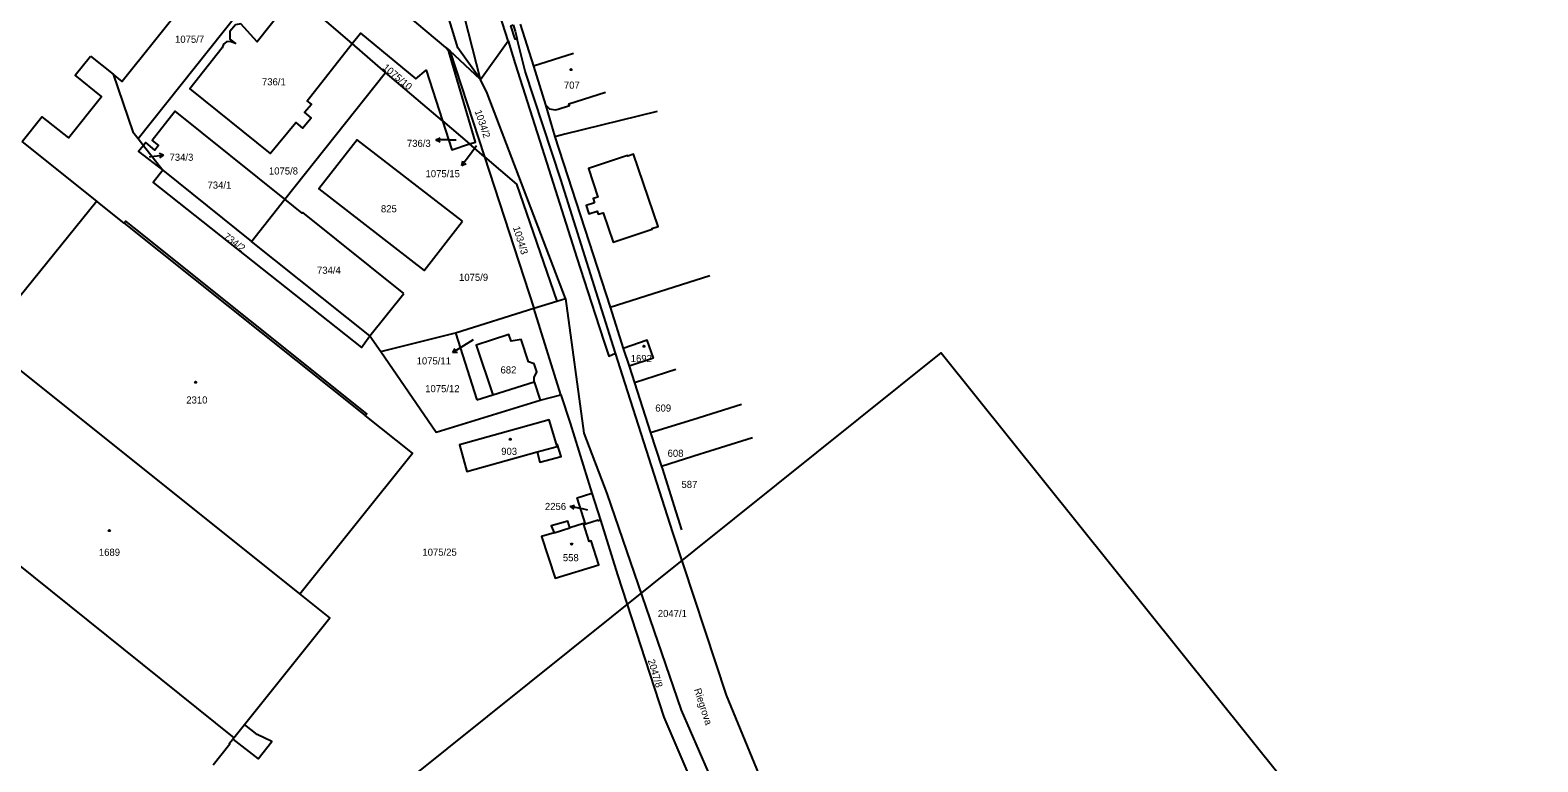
# Model space of a CAD drawing. Extents: x -793666 to -785424, y -1118958 to -1108761.
# Drawn here: x -792344.1 to -791983.5, y -1109605.6 to -1109430.6 of the extents above; entities that cross this region are included whole.
import ezdxf

# ---------------------------------------------------------------- set-up
doc = ezdxf.new("R2010")
doc.units = 0
for name, color, linetype in [('1_2000 - úřady', 7, 'Continuous'), ('Hranice parcel', 7, 'Continuous'), ('Parcelní čísla', 7, 'Continuous'), ('Pop  PČ popisy', 7, 'Continuous'), ('Vnitřní kresba', 7, 'Continuous'), ('Značky budov', 7, 'Continuous')]:
    doc.layers.add(name, color=color, linetype=linetype)

msp = doc.modelspace()

# ---------------------------------------------------------------- linework, layer by layer
at = {"layer": '1_2000 - úřady'}
msp.add_lwpolyline([(-791938.08, -1109742.36), (-792598.01, -1110271.46), (-792786.15, -1110036.8), (-792126.22, -1109507.7)], close=True, dxfattribs=at)
at = {"layer": 'Hranice parcel'}
for p, q in [((-792229.77, -1109433.14), (-792236.48, -1109411.88)), ((-792318.27, -1109456.46), (-792286.75, -1109416.81)), ((-792267.06, -1109433.78), (-792280.76, -1109421.97)), ((-792259.07, -1109440.66), (-792267.06, -1109433.78)), ((-792244.63, -1109434.67), (-792243.68, -1109435.47)), ((-792236.38, -1109442.35), (-792229.77, -1109433.14)), ((-792229.77, -1109433.14), (-792228.05, -1109438.6)), ((-792329.67, -1109436.74), (-792324.22, -1109441.09)), ((-792236.38, -1109442.35), (-792243.68, -1109435.47)), ((-792243.68, -1109435.47), (-792235.42, -1109460.82)), ((-792283.18, -1109471), (-792259.07, -1109440.66)), ((-792245.44, -1109452.28), (-792259.07, -1109440.66)), ((-792220.81, -1109448.38), (-792218.56, -1109456.03)), ((-792245.44, -1109452.28), (-792238.98, -1109457.78)), ((-792194.09, -1109449.98), (-792216.18, -1109455.44)), ((-792318.27, -1109456.46), (-792316.97, -1109458.11)), ((-792216.18, -1109455.44), (-792218.56, -1109456.03)), ((-792218.56, -1109456.03), (-792205.34, -1109496.82)), ((-792328.15, -1109471.45), (-792346.01, -1109457.18)), ((-792316.97, -1109458.11), (-792312.32, -1109464.02)), ((-792235.42, -1109460.82), (-792238.98, -1109457.78)), ((-792235.42, -1109460.82), (-792223.61, -1109497.07)), ((-792312.32, -1109464.02), (-792291.18, -1109481.07)), ((-792291.18, -1109481.07), (-792283.18, -1109471)), ((-792328.15, -1109471.45), (-792350.22, -1109498.79)), ((-792262.87, -1109503.68), (-792291.18, -1109481.07)), ((-792205.34, -1109496.82), (-792181.48, -1109489.21)), ((-792262.87, -1109503.68), (-792254.68, -1109493.51)), ((-792223.61, -1109497.07), (-792218.11, -1109495.38)), ((-792218.11, -1109495.38), (-792216.04, -1109494.77)), ((-792242.33, -1109502.95), (-792223.61, -1109497.07)), ((-792217.14, -1109517.79), (-792223.61, -1109497.07)), ((-792205.34, -1109496.82), (-792202.22, -1109506.7)), ((-792260.21, -1109507.41), (-792242.33, -1109502.95)), ((-792242.33, -1109502.95), (-792237.24, -1109519)), ((-792279.6, -1109565.4), (-792355.19, -1109504.95)), ((-792262.87, -1109503.68), (-792260.21, -1109507.41)), ((-792202.22, -1109506.7), (-792200.82, -1109510.9)), ((-792195, -1109509.05), (-792200.82, -1109510.9)), ((-792237.24, -1109519), (-792233.43, -1109517.79)), ((-792233.43, -1109517.79), (-792223.5, -1109514.64)), ((-792223.5, -1109514.64), (-792222.14, -1109519.07)), ((-792222.14, -1109519.07), (-792217.14, -1109517.79)), ((-792195.72, -1109526.9), (-792193.09, -1109534.9)), ((-792378.05, -1109533.41), (-792295.37, -1109599.83)), ((-792209.71, -1109541.3), (-792207.68, -1109547.79)), ((-792190.54, -1109542.98), (-792188.3, -1109550.06)), ((-792295.37, -1109599.83), (-792295.65, -1109600.16))]:
    msp.add_line(p, q, dxfattribs=at)
for points in [[(-792236.38, -1109442.35), (-792241.83, -1109434.76), (-792242.07, -1109433.96), (-792248.3, -1109413.31), (-792257.02, -1109387.35), (-792267.42, -1109371.57), (-792268.26, -1109370.15)], [(-792244.63, -1109434.67), (-792258.54, -1109423), (-792272.12, -1109411.1)], [(-792299.18, -1109414.18), (-792322.06, -1109442.82), (-792324.22, -1109441.09)], [(-792280.76, -1109421.97), (-792289.81, -1109433.34), (-792293.7, -1109429.04), (-792295.01, -1109429.27), (-792296.35, -1109430.89), (-792296.29, -1109432.67), (-792294.98, -1109433.75), (-792296.26, -1109433.28), (-792297.14, -1109433.34), (-792297.85, -1109433.91), (-792298.14, -1109434.81), (-792305.89, -1109444.59), (-792286.66, -1109460.05), (-792280.52, -1109452.67), (-792278.92, -1109454), (-792276.86, -1109451.51), (-792278.46, -1109450.19), (-792276.83, -1109448.23), (-792277.84, -1109447.42), (-792267.06, -1109433.78)], [(-792267.06, -1109433.78), (-792265.08, -1109431.27), (-792251.85, -1109442.17), (-792249.33, -1109440.1), (-792245.44, -1109452.28)], [(-792227.59, -1109432.68), (-792228.11, -1109432.7), (-792229.13, -1109429.49), (-792228.52, -1109429.29)], [(-792228.52, -1109429.29), (-792228.07, -1109430.77), (-792227.59, -1109432.68)], [(-792226.9, -1109429.15), (-792223.72, -1109439.13), (-792220.81, -1109448.38)], [(-792238.98, -1109457.78), (-792237.53, -1109457.31), (-792243.95, -1109435.69), (-792244.63, -1109434.67)], [(-792204.07, -1109507.78), (-792207.35, -1109497.45), (-792217.13, -1109466.3), (-792225.67, -1109440.37), (-792225.83, -1109439.74), (-792227.59, -1109432.68)], [(-792346.01, -1109457.18), (-792341.33, -1109451.32), (-792334.95, -1109456.33), (-792327.06, -1109446.44), (-792333.34, -1109441.33), (-792329.67, -1109436.74)], [(-792228.05, -1109438.6), (-792221.1, -1109460.59), (-792213.33, -1109485.05), (-792208.98, -1109498.53), (-792206.82, -1109505.15), (-792205.71, -1109508.55), (-792204.07, -1109507.78)], [(-792324.22, -1109441.09), (-792319.52, -1109454.87), (-792318.27, -1109456.46)], [(-792216.04, -1109494.77), (-792234.81, -1109445.64), (-792236.38, -1109442.35)], [(-792220.81, -1109448.38), (-792219.9, -1109449.36), (-792218.42, -1109449.63), (-792217.76, -1109449.42), (-792215.11, -1109448.58), (-792215.24, -1109448.15), (-792206.5, -1109445.38)], [(-792283.18, -1109471), (-792309.4, -1109449.94), (-792314.92, -1109456.94), (-792313.38, -1109458.14), (-792314.26, -1109459.26), (-792316.4, -1109457.43), (-792316.97, -1109458.11)], [(-792245.44, -1109452.28), (-792243.24, -1109459.17), (-792238.98, -1109457.78)], [(-792316.97, -1109458.11), (-792318.18, -1109459.57), (-792312.32, -1109464.02)], [(-792240.71, -1109476.24), (-792265.9, -1109456.76), (-792275.02, -1109468.52), (-792249.86, -1109488.05), (-792240.71, -1109476.24)], [(-792209.1, -1109471.85), (-792211.1, -1109472.52), (-792210.43, -1109474.51), (-792208.44, -1109473.84), (-792208.19, -1109474.6), (-792207.03, -1109474.22), (-792204.68, -1109481.25), (-792195.32, -1109478.16), (-792195.37, -1109478.02), (-792193.91, -1109477.54), (-792199.75, -1109460.2), (-792201.16, -1109460.67), (-792201.21, -1109460.53), (-792210.55, -1109463.67), (-792208.28, -1109470.47), (-792209.44, -1109470.85), (-792209.1, -1109471.85)], [(-792235.42, -1109460.82), (-792227.73, -1109467.37), (-792218.11, -1109495.38)], [(-792312.32, -1109464.02), (-792314.7, -1109467), (-792264.82, -1109506.43), (-792262.87, -1109503.68)], [(-792254.68, -1109493.51), (-792278.86, -1109474.2), (-792278.99, -1109474.36), (-792283.18, -1109471)], [(-792279.6, -1109565.4), (-792252.67, -1109531.71), (-792263.92, -1109522.73), (-792263.58, -1109522.3), (-792319.23, -1109477.86), (-792321.23, -1109476.26), (-792321.58, -1109476.7), (-792327.49, -1109471.98), (-792328.15, -1109471.45)], [(-792216.04, -1109494.77), (-792211.63, -1109526.92), (-792206.15, -1109541.38), (-792188.4, -1109593.25), (-792177.58, -1109617.9), (-792162.42, -1109637.81), (-792158.94, -1109642.01), (-792160.24, -1109643.3), (-792162, -1109644.38)], [(-792223.5, -1109514.64), (-792223.53, -1109513.66), (-792222.86, -1109512.32), (-792223.5, -1109510.33), (-792224.86, -1109509.85), (-792226.61, -1109504.52), (-792229.04, -1109504.98), (-792229.56, -1109503.37), (-792237.41, -1109505.9), (-792233.43, -1109517.79)], [(-792195, -1109509.05), (-792196.47, -1109504.73), (-792202.22, -1109506.7)], [(-792260.21, -1109507.41), (-792246.98, -1109526.69), (-792222.14, -1109519.07)], [(-792153.37, -1109630.69), (-792168.6, -1109611.32), (-792177.54, -1109589.6), (-792190.39, -1109550.74), (-792201.74, -1109515.1), (-792204.07, -1109507.78)], [(-792200.82, -1109510.9), (-792199.56, -1109514.95), (-792195.72, -1109526.9)], [(-792217.14, -1109517.79), (-792214.92, -1109524.55), (-792209.71, -1109541.3)], [(-792173.97, -1109520.08), (-792185.62, -1109523.73), (-792195.72, -1109526.9)], [(-792218.05, -1109529.51), (-792218.22, -1109529.57), (-792219.94, -1109523.79), (-792241.42, -1109529.73), (-792239.61, -1109536.1), (-792222.84, -1109531.45), (-792222.17, -1109533.89), (-792217.04, -1109532.53), (-792218.05, -1109529.51)], [(-792171.33, -1109528.08), (-792182.81, -1109531.68), (-792183.84, -1109532), (-792193.09, -1109534.9)], [(-792193.09, -1109534.9), (-792192.87, -1109535.59), (-792190.54, -1109542.98)], [(-792207.68, -1109547.79), (-792208.17, -1109547.94), (-792208.22, -1109547.8), (-792211.26, -1109548.75), (-792213.24, -1109542.41), (-792209.71, -1109541.3)], [(-792214.99, -1109549.58), (-792215.48, -1109548.01), (-792219.45, -1109549.11), (-792218.77, -1109550.78), (-792221.75, -1109551.71), (-792218.55, -1109561.63), (-792208.1, -1109558.47), (-792209.93, -1109552.72), (-792210.36, -1109552.86), (-792211.71, -1109548.55), (-792214.99, -1109549.58)], [(-792207.68, -1109547.79), (-792203.58, -1109560.85), (-792192.49, -1109594.88), (-792186.8, -1109608.25)], [(-792292.8, -1109596.62), (-792272.41, -1109571.15), (-792279.6, -1109565.4)], [(-792295.65, -1109600.16), (-792289.59, -1109604.87), (-792286.27, -1109600.7), (-792289.83, -1109599.05), (-792292.8, -1109596.62)], [(-792300.29, -1109606.28), (-792296.3, -1109601.29), (-792296.46, -1109601.17), (-792295.65, -1109600.16)]]:
    msp.add_lwpolyline(points, dxfattribs=at)
at = {"layer": 'Pop  PČ popisy'}
for p, q in [((-792247.03, -1109456.78), (-792246.03, -1109456.28)), ((-792312.21, -1109460.49), (-792313.26, -1109460.09)), ((-792244.03, -1109456.78), (-792247.03, -1109456.78)), ((-792247.03, -1109456.78), (-792246.03, -1109457.28)), ((-792244.03, -1109456.78), (-792242.21, -1109456.78)), ((-792237.33, -1109458.25), (-792239.03, -1109460.51)), ((-792315.56, -1109460.84), (-792315.2, -1109460.8)), ((-792315.2, -1109460.8), (-792312.21, -1109460.49)), ((-792312.21, -1109460.49), (-792313.16, -1109461.09)), ((-792239.03, -1109460.51), (-792240.84, -1109462.91)), ((-792240.84, -1109462.91), (-792240.63, -1109461.81)), ((-792240.84, -1109462.91), (-792239.83, -1109462.41)), ((-792240.44, -1109506.08), (-792242.98, -1109507.67)), ((-792242.98, -1109507.67), (-792242.4, -1109506.72)), ((-792238.16, -1109504.63), (-792240.44, -1109506.08)), ((-792242.98, -1109507.67), (-792241.87, -1109507.56)), ((-792214.95, -1109544.47), (-792213.86, -1109544.18)), ((-792212.01, -1109545.09), (-792214.95, -1109544.47)), ((-792214.95, -1109544.47), (-792214.07, -1109545.16)), ((-792210.72, -1109545.36), (-792212.01, -1109545.09))]:
    msp.add_line(p, q, dxfattribs=at)
at = {"layer": 'Vnitřní kresba'}
for p, q in [((-792236.38, -1109442.35), (-792240.17, -1109427.35)), ((-792214.11, -1109436.11), (-792223.72, -1109439.13)), ((-792321.58, -1109476.7), (-792263.92, -1109522.73)), ((-792189.64, -1109511.71), (-792199.56, -1109514.95)), ((-792222.84, -1109531.45), (-792218.05, -1109530.13)), ((-792218.05, -1109530.13), (-792218.22, -1109529.57)), ((-792218.77, -1109550.78), (-792214.99, -1109549.58)), ((-792295.37, -1109599.83), (-792292.8, -1109596.62))]:
    msp.add_line(p, q, dxfattribs=at)
at = {"layer": 'Značky budov'}
for centre in [(-792214.71, -1109439.98), (-792197.27, -1109506.15), (-792304.53, -1109514.77), (-792229.27, -1109528.41), (-792325.15, -1109550.24), (-792214.56, -1109553.49)]:
    msp.add_circle(centre, 0.175, dxfattribs=at)

# ---------------------------------------------------------------- texts
at = {"layer": 'Parcelní čísla'}
for s, p in [('1075/7', (-792309.43, -1109433.58)), ('736/1', (-792288.64, -1109443.75)), ('707', (-792216.42, -1109444.55)), ('734/3', (-792310.75, -1109461.8)), ('736/3', (-792253.97, -1109458.48)), ('1075/8', (-792286.98, -1109465.08)), ('734/1', (-792301.66, -1109468.46)), ('1075/15', (-792249.52, -1109465.73)), ('825', (-792260.19, -1109474.12)), ('734/4', (-792275.48, -1109488.83)), ('1075/9', (-792241.5, -1109490.52)), ('1075/11', (-792251.65, -1109510.52)), ('1692', (-792200.44, -1109509.94)), ('682', (-792231.58, -1109512.67)), ('1075/12', (-792249.6, -1109517.15)), ('2310', (-792306.74, -1109519.86)), ('609', (-792194.57, -1109521.79)), ('903', (-792231.42, -1109532.15)), ('608', (-792191.62, -1109532.61)), ('587', (-792188.3, -1109540.06)), ('2256', (-792220.96, -1109545.33)), ('1689', (-792327.65, -1109556.29)), ('1075/25', (-792250.27, -1109556.27)), ('558', (-792216.67, -1109557.58)), ('2047/1', (-792193.96, -1109570.93))]:
    msp.add_text(s, height=1.7, dxfattribs=at).set_placement(p)
for s, rotation, p in [('1075/10', 320, (-792259.91, -1109439.73)), ('1034/2', 289, (-792237.8, -1109449.96)), ('1034/3', 287, (-792228.62, -1109477.74)), ('734/2', 323, (-792297.98, -1109480.22)), ('2047/8', 287, (-792196.38, -1109581.32))]:
    msp.add_text(s, height=1.7, rotation=rotation, dxfattribs=at).set_placement(p)
at = {"layer": 'Pop  PČ popisy'}
msp.add_text('Riegrova', height=1.7, rotation=288, dxfattribs=at).set_placement((-792185.31, -1109588.27))

doc.saveas('drawing.dxf')
